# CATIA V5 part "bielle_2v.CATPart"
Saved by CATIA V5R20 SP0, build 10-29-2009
Part number: bielle_2v
Bounding box of the stored display mesh (mm): x 58.502 to 188.501, y 67.858 to 217.911, z 116.842 to 136.842
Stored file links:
  D:\ecole\thinkmotion\IAO\bielle_2v.CATPart
  D:\ecole\thinkmotion\IAO\mecanisme coulisseau.CATProduct
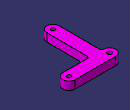
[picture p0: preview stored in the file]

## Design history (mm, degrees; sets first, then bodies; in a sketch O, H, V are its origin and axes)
External parameters (linked from other documents)
  External.rayon_pivot_bielle = 5 mm
Set1
  Plane1: linked copy from another document
  Point1 to Point6: linked copy from another document
  Line1: linked copy from another document
  Plane2: linked copy from another document
Body1 (main body)
  Sketch1 on Plane1, origin (0, 0, 136.8423), H (1, 0, 0), V (0, -1, 0)
    arc A1 centre (173.5015, -202.6401) radius 15 from (173.4608, -187.6401) to (173.5422, -217.64) cw
    point P1 (173.5015, -202.6401)
    point P2 (173.4608, -187.6401)
    point P3 (173.5422, -217.64)
    reference projected point E1 (173.5015, -202.6401) from Point1
    reference projected point E2 (188.5014, -202.5994) from Point2
    arc A2 centre (73.5019, -202.9115) radius 15 from (73.4612, -187.9115) to (73.5426, -217.9114) ccw
    point P4 (73.5019, -202.9115)
    point P5 (73.4612, -187.9115)
    point P6 (73.5426, -217.9114)
    reference projected point E3 (73.5019, -202.9115) from Point3
    reference projected point E4 (58.5019, -202.9522) from Point4
    line L1 (173.4608, -187.6401) -> (108.461, -187.8165)
    point P7 (173.4608, -187.6401)
    point P8 (73.4612, -187.9115)
    line L2 (173.5422, -217.64) -> (73.5426, -217.9114)
    point P9 (173.5422, -217.64)
    point P10 (73.5426, -217.9114)
    arc A3 centre (93.1761, -82.8576) radius 15 from (108.1761, -82.8169) to (78.1762, -82.8983) ccw
    point P11 (93.1761, -82.8576)
    point P12 (78.1762, -82.8983)
    point P13 (108.1761, -82.8169)
    reference projected point E5 (93.1761, -82.8576) from Point5
    reference projected point E6 (93.1354, -67.8577) from Point6
    line L3 (108.461, -187.8165) -> (108.1761, -82.8169)
    point P15 (108.1761, -82.8169)
    reference projected line E7 through (93.0835, -48.7115) direction (-0.0027, 1) from Line1
    line L4 (78.1762, -82.8983) -> (78.4611, -187.898)
    point P16 (78.1762, -82.8983)
    point P17 (78.4611, -187.898)
    reference projected line E8 through (93.0835, -48.7115) direction (-0.0027, 1) from Line1
    line L5 (78.4611, -187.898) -> (73.4612, -187.9115)
    coincidence: P1 E1, A1 E2, P4 E3, A2 E4, P7 P2, P8 P5, P10 P6, P9 P3, P11 E5, A3 E6, P15 P13, P16 P12, P17 L1, L1 L5
    tangency: A1 L2, L2 A2, L1 A1, L1 A2, A3 L3, A3 L4
    parallelism: L3 E7, L4 E8
  Pad1: profile Sketch1, direction (0, 0, -1), up to Plane2
  Fillet1: radius 5, on edge [face of Pad1 from Sketch1.L3 | face of Pad1 from Sketch1.L1]
  Fillet2: radius 5, on edge [face of Pad1 from Sketch1.L5 | face of Pad1 from Sketch1.L4]
  Sketch2 on start face of Pad1, origin (100, 0, 136.8423), H (1, 0, 0), V (0, 1, 0)
    point P1 (73.5015, 202.6401)
    reference projected point E1 (73.5015, 202.6401) from Point1
    coincidence: E1 P1
  Hole1: placed by Sketch2, at (173.5015, 202.6401, 136.8423) direction (0, 0, -1), diameter 10 {= External.rayon_pivot_bielle *2}, up to Plane2
  Sketch3 on start face of Pad1, origin (0, 0, 136.8423), H (1, 0, 0), V (0, 1, 0)
    point P1 (73.5019, 202.9115)
    reference projected point E1 (73.5019, 202.9115) from Point3
    coincidence: E1 P1
  Hole2: placed by Sketch3, at (73.5019, 202.9115, 136.8423) direction (0, 0, -1), diameter 10 {= External.rayon_pivot_bielle *2}, up to Plane2
  Sketch4 on start face of Pad1, origin (20, 80, 136.8423), H (1, 0, 0), V (0, 1, 0)
    point P1 (73.1761, 2.8576)
    reference projected point E1 (73.1761, 2.8576) from Point5
    coincidence: E1 P1
  Hole3: placed by Sketch4, at (93.1761, 82.8576, 136.8423) direction (0, 0, -1), diameter 10 {= External.rayon_pivot_bielle *2}, up to Plane2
